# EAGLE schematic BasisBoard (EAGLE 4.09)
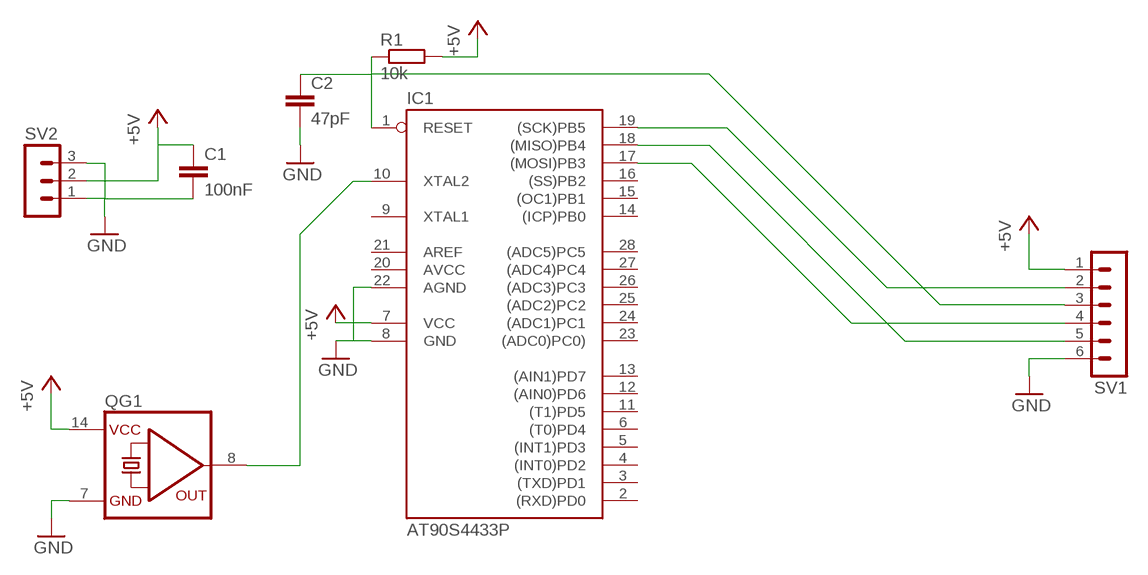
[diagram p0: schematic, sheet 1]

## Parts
C1  100nF  C5/3  [C5B3]
C2  47pF  C2,5-3  [C2.5-3]
IC1  AT90S4433P  [DIL28-3]
QG1  QG5860  [DIL14S]
R1  10k  R-EU_0207/10  [0207/10]
SV1  MA06-1  [MA06-1]
SV2  MA03-1  [MA03-1]

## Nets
+5V: C1.1 IC1.7(VCC) QG1.14(VCC) R1.2 SV1.1 SV2.2
GND: C1.2 C2.2 IC1.8(GND) IC1.22(AGND) QG1.7(GND) SV1.6 SV2.1 SV2.3
N$1: IC1.10(XTAL2) QG1.8(OUT)
N$2: C2.1 IC1.1(RESET) R1.1 SV1.3
N$3: IC1.19((SCK)PB5) SV1.2
N$4: IC1.18((MISO)PB4) SV1.5
N$5: IC1.17((MOSI)PB3) SV1.4
Unconnected: IC1.2((RXD)PD0) IC1.3((TXD)PD1) IC1.4((INT0)PD2) IC1.5((INT1)PD3) IC1.6((T0)PD4) IC1.9(XTAL1) IC1.11((T1)PD5) IC1.12((AIN0)PD6) IC1.13((AIN1)PD7) IC1.14((ICP)PB0) IC1.15((OC1)PB1) IC1.16((SS)PB2) IC1.23((ADC0)PC0)) IC1.24((ADC1)PC1) IC1.25((ADC2)PC2) IC1.26((ADC3)PC3) IC1.27((ADC4)PC4) IC1.28((ADC5)PC5)

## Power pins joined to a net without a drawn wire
AREF: IC1.21(AREF)
AVCC: IC1.20(AVCC)

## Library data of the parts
C1 C2 = capacitor-wima:C: CAPACITOR
IC1 = atmel:AT90S4433: MICROCONTROLLER 4 Kbytes FLASH 128 bytes SRAM 256 bytes EEPROM UART 6-channel 10 bit ADC
QG1 = crystal:QG5860: CRYSTAL RESONATOR
R1 = rcl:R-EU_: RESISTOR, European symbol
SV1 = con-lstb:MA06-1: PIN HEADER
SV2 = con-lstb:MA03-1: PIN HEADER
